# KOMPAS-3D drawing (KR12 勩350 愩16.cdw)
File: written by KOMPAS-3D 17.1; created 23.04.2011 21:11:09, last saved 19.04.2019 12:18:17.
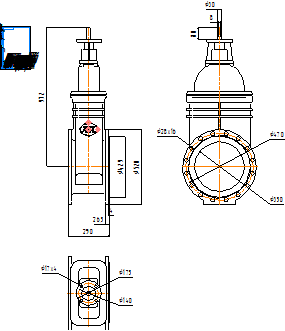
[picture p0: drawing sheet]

Sheet 1: A4, portrait

Title block, sheet 1: name: KR12 Ду350 Ру16; material: Внимание! Данный продукт является объектом авторского права ООО «Торговый Дом АДЛ». / Запрещается изменение, копирование, распространение / (в том числе путем копирования на другие сайты и ресурсы в Интернете) / или любое иное использование информации и объектов без предварительного / согласия правообладателя (ООО «Торговый Дом АДЛ»).; scale: 1:1; sheets: 1; organisation: ООО "Торговый дом АДЛ"; sheet format: A4; stored path: \\adlc.lan\data\АДЛ_ПКД\3D-модели\ADL production\Клиновые задвижки серии KR ГРАНАР\Клиновые задвижки KR12\KOMPAS 2D\KR12 Ду350 Ру16.cdw

Views: Спереди 4, Проекционный вид 5
Dimensions and other numbers on the sheet: 290; 26,5; 4; 972; 429; 520; 175; 17; 140; 1:1; 1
